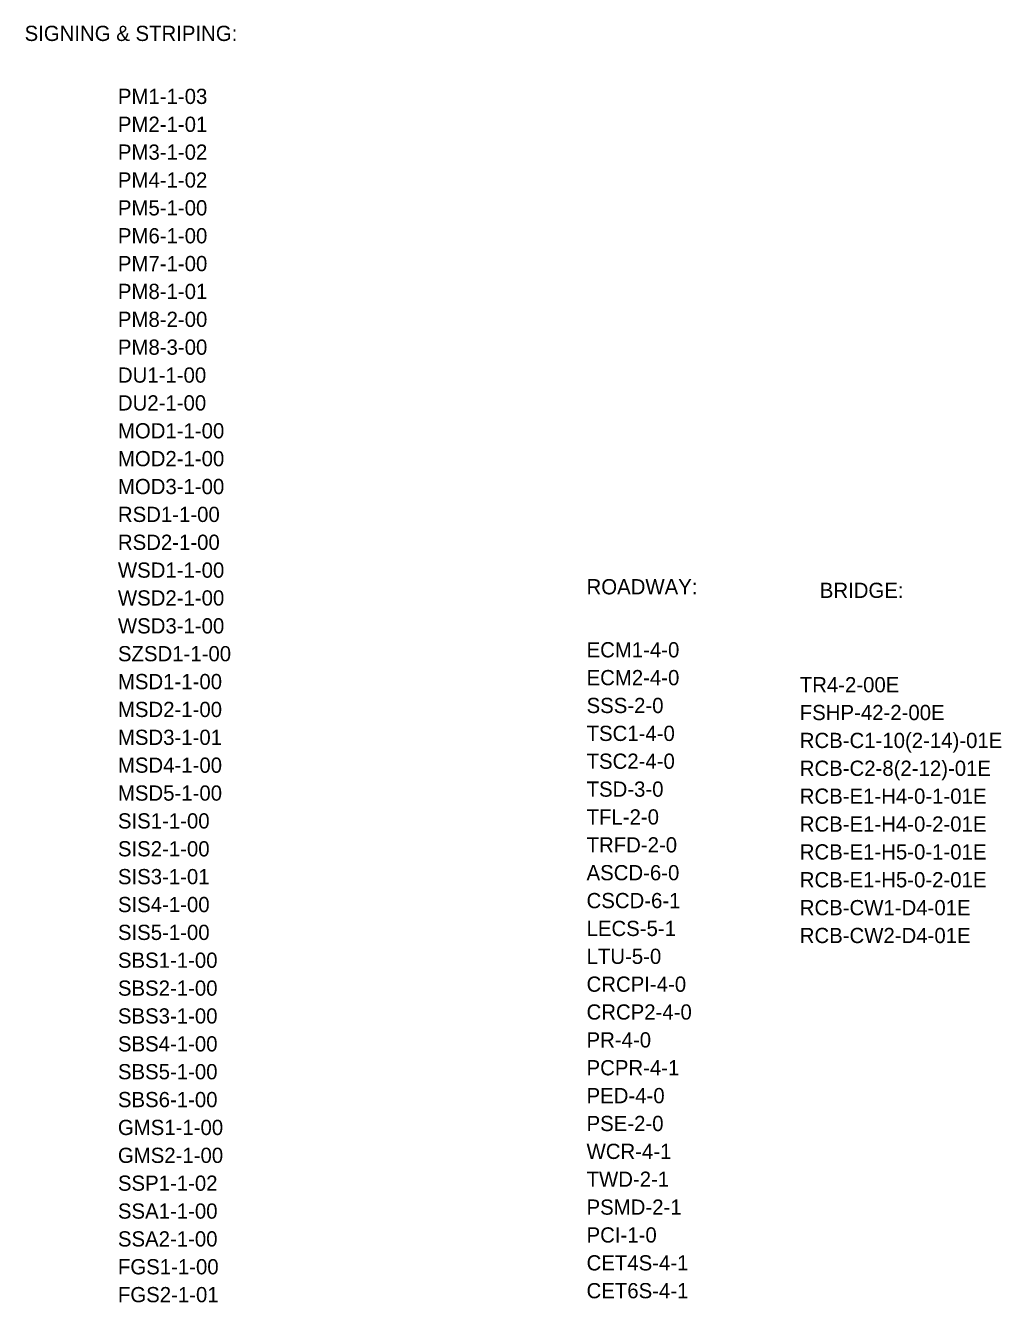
# Model space of a CAD drawing. Extents: x 11.3 to 109.4, y -18.4 to 58.
# Drawn here: x 93.42 to 109.44, y 34.08 to 55.05 of the extents above; entities that cross this region are included whole.
import ezdxf

# ---------------------------------------------------------------- set-up
doc = ezdxf.new("R2010")
doc.units = 0
doc.layers.add('PR_Improvements_Txt', color=7, linetype='Continuous')

msp = doc.modelspace()

# ---------------------------------------------------------------- texts
at = {"layer": 'PR_Improvements_Txt'}
for s, p in [('SIGNING & STRIPING:', (93.403, 54.793)), ('PM1-1-03', (94.935, 53.759)), ('PM2-1-01', (94.935, 53.301)), ('PM3-1-02', (94.935, 52.844)), ('PM4-1-02', (94.935, 52.386)), ('PM5-1-00', (94.935, 51.929)), ('PM6-1-00', (94.935, 51.471)), ('PM7-1-00', (94.935, 51.014)), ('PM8-1-01', (94.935, 50.557)), ('PM8-2-00', (94.935, 50.099)), ('PM8-3-00', (94.935, 49.642)), ('DU1-1-00', (94.935, 49.184)), ('DU2-1-00', (94.935, 48.727)), ('MOD1-1-00', (94.935, 48.269)), ('MOD2-1-00', (94.935, 47.812)), ('MOD3-1-00', (94.935, 47.354)), ('RSD1-1-00', (94.935, 46.897)), ('RSD2-1-00', (94.935, 46.439)), ('WSD1-1-00', (94.935, 45.982)), ('ROADWAY:', (102.629, 45.709)), ('WSD2-1-00', (94.935, 45.525)), ('BRIDGE:', (106.458, 45.65)), ('WSD3-1-00', (94.935, 45.067)), ('SZSD1-1-00', (94.935, 44.61)), ('ECM1-4-0', (102.629, 44.674)), ('ECM2-4-0', (102.629, 44.217)), ('MSD1-1-00', (94.935, 44.152)), ('TR4-2-00E', (106.129, 44.101)), ('MSD2-1-00', (94.935, 43.695)), ('SSS-2-0', (102.629, 43.76)), ('FSHP-42-2-00E', (106.129, 43.644)), ('MSD3-1-01', (94.935, 43.237)), ('TSC1-4-0', (102.629, 43.302)), ('RCB-C1-10(2-14)-01E', (106.129, 43.186)), ('MSD4-1-00', (94.935, 42.78)), ('TSC2-4-0', (102.629, 42.845)), ('RCB-C2-8(2-12)-01E', (106.129, 42.729)), ('MSD5-1-00', (94.935, 42.322)), ('TSD-3-0', (102.629, 42.387)), ('RCB-E1-H4-0-1-01E', (106.129, 42.271)), ('TFL-2-0', (102.629, 41.93)), ('SIS1-1-00', (94.935, 41.865)), ('RCB-E1-H4-0-2-01E', (106.129, 41.814)), ('TRFD-2-0', (102.629, 41.472)), ('SIS2-1-00', (94.935, 41.407)), ('RCB-E1-H5-0-1-01E', (106.129, 41.356)), ('SIS3-1-01', (94.935, 40.95)), ('ASCD-6-0', (102.629, 41.015)), ('RCB-E1-H5-0-2-01E', (106.129, 40.899)), ('SIS4-1-00', (94.935, 40.492)), ('CSCD-6-1', (102.629, 40.557)), ('RCB-CW1-D4-01E', (106.129, 40.441)), ('SIS5-1-00', (94.935, 40.035)), ('LECS-5-1', (102.629, 40.1)), ('RCB-CW2-D4-01E', (106.129, 39.984)), ('SBS1-1-00', (94.935, 39.578)), ('LTU-5-0', (102.629, 39.642)), ('CRCPI-4-0', (102.629, 39.185)), ('SBS2-1-00', (94.935, 39.12)), ('SBS3-1-00', (94.935, 38.663)), ('CRCP2-4-0', (102.629, 38.728)), ('SBS4-1-00', (94.935, 38.205)), ('PR-4-0', (102.629, 38.27)), ('SBS5-1-00', (94.935, 37.748)), ('PCPR-4-1', (102.629, 37.813)), ('SBS6-1-00', (94.935, 37.29)), ('PED-4-0', (102.629, 37.355)), ('PSE-2-0', (102.629, 36.898)), ('GMS1-1-00', (94.935, 36.833)), ('WCR-4-1', (102.629, 36.44)), ('GMS2-1-00', (94.935, 36.375)), ('SSP1-1-02', (94.935, 35.918)), ('TWD-2-1', (102.629, 35.983)), ('SSA1-1-00', (94.935, 35.46)), ('PSMD-2-1', (102.629, 35.525)), ('SSA2-1-00', (94.935, 35.003)), ('PCI-1-0', (102.629, 35.068)), ('FGS1-1-00', (94.935, 34.546)), ('CET4S-4-1', (102.629, 34.61)), ('CET6S-4-1', (102.629, 34.153)), ('FGS2-1-01', (94.935, 34.088))]:
    msp.add_text(s, height=0.25, dxfattribs=at).set_placement(p)

doc.saveas('drawing.dxf')
